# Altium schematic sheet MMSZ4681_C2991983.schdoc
size 127 x 101 mm
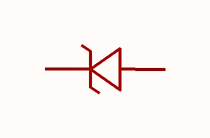
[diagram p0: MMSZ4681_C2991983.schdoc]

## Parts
D?  mmsz4681  [SOD-123_L2.7-W1.6-LS3.7-RD]  (value not drawn)

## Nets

Not connected (* = marked no-connect by the designer): D? 1(C) 2(A)

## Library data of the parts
D? = mmsz4681: 二极管配置:1个独立式;稳压值(标称值):2.4V;稳压值(范围):2.28V~2.52V;耗散功率(Pd):500mW;; Manufacturer: CJ(江苏长电/长晶); Symbol: MMSZ4681_C2991983; AddInBom: yes; ModelId: ad7e39f9e5534b3c96ffdc5532ebb493; ModelName: SOD-123_L2.7-W1.6-H1.4-LS3.7; ModelTransform: 146.026,62.992,0,180,0,0,0.0005,0,0; Diode Configuration: 1个独立式; Zener Voltage(Nom): 2.4V; Reverse Leakage Current (Ir): 2uA@1V; Pd - Power Dissipation: 500mW; Operating Junction Temperature Range: -55℃~+150℃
